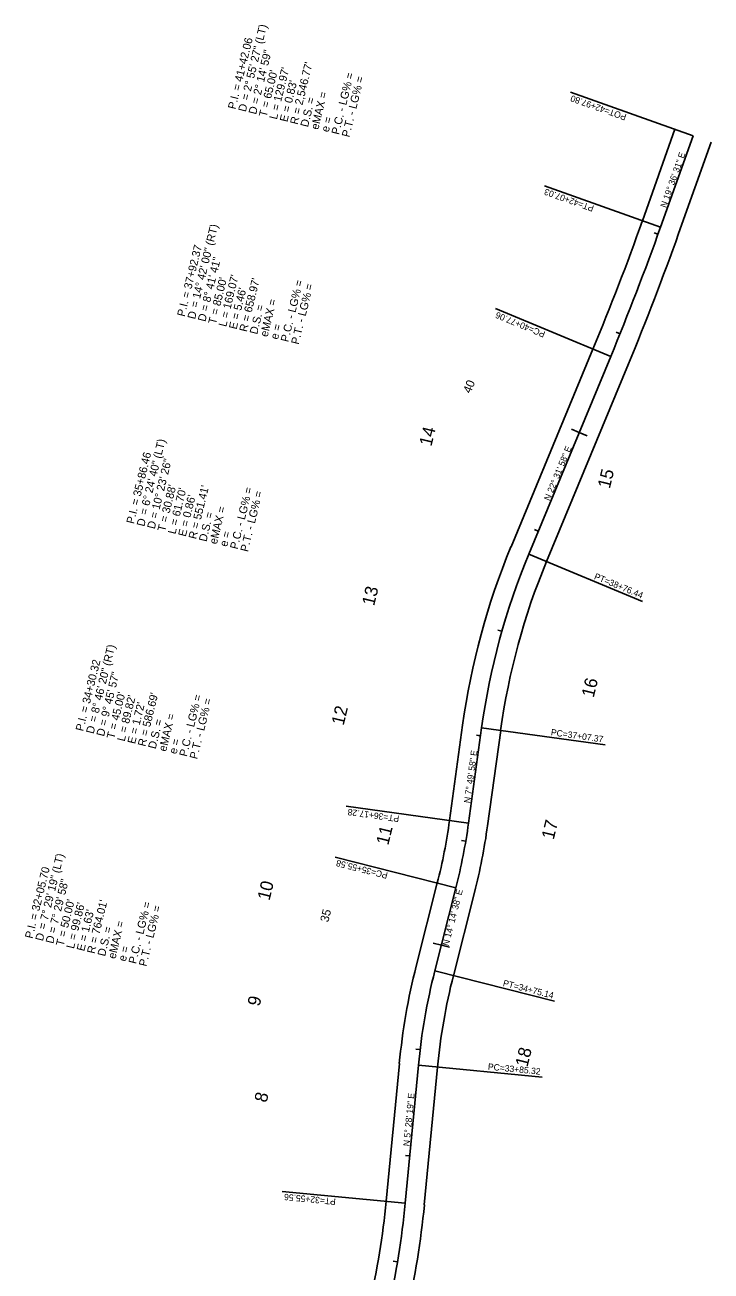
# Model space of a CAD drawing. Extents: x 1579440 to 1580937, y 1116374 to 1119566.
# Drawn here: x 1580144 to 1580787, y 1118399 to 1119566 of the extents above; entities that cross this region are included whole.
import ezdxf

# ---------------------------------------------------------------- set-up
doc = ezdxf.new("R2010")
doc.units = 0
for name, color, linetype in [('RD_HC_Cl', 7, 'Continuous'), ('RD_HC_Data', 7, 'Continuous'), ('RD_HC_Data_Tic', 7, 'Continuous'), ('RD_HC_TX_Sta50', 7, 'Continuous'), ('RD_PD_CstnLmt_TX', 7, 'Continuous'), ('RD_XS_Binder', 7, 'Continuous')]:
    doc.layers.add(name, color=color, linetype=linetype)

msp = doc.modelspace()

# ---------------------------------------------------------------- linework, layer by layer
at = {"layer": 'RD_HC_Cl'}
for p, q in [((1580739.9, 1119376.9), (1580770.4, 1119462.4)), ((1580739.9, 1119376.9), (1580770.4, 1119462.4)), ((1580616.3, 1119070.3), (1580693.2, 1119255.6)), ((1580616.3, 1119070.3), (1580693.2, 1119255.6)), ((1580559.9, 1118818.4), (1580572.1, 1118907.6)), ((1580559.9, 1118818.4), (1580572.1, 1118907.6)), ((1580528.3, 1118679.9), (1580548, 1118757.8)), ((1580528.3, 1118679.9), (1580548, 1118757.8)), ((1580500.5, 1118462.3), (1580512.9, 1118591.5)), ((1580500.5, 1118462.3), (1580512.9, 1118591.5))]:
    msp.add_line(p, q, dxfattribs=at)
for centre, radius, start, end in [((1578340.8, 1120231.6), 2546.8, 337.4673, 340.3913), ((1578340.8, 1120231.6), 2546.8, 337.4673, 340.3913), ((1581225, 1118817.8), 659, 157.4673, 172.1672), ((1581225, 1118817.8), 659, 157.4673, 172.1672), ((1580013.6, 1118893.5), 551.4, 345.756, 352.1672), ((1580013.6, 1118893.5), 551.4, 345.756, 352.1672), ((1581096.9, 1118535.5), 586.7, 165.756, 174.5281), ((1581096.9, 1118535.5), 586.7, 165.756, 174.5281), ((1579740, 1118535.1), 764, 347.0395, 354.5281), ((1579740, 1118535.1), 764, 347.0395, 354.5281)]:
    msp.add_arc(centre, radius, start, end, dxfattribs=at)
at = {"layer": 'RD_HC_Data'}
for p, q in [((1580770.4, 1119462.4), (1580655.4, 1119503.4)), ((1580739.9, 1119376.9), (1580631.1, 1119415.7)), ((1580693.2, 1119255.6), (1580585.2, 1119300.5)), ((1580616.3, 1119070.3), (1580723.1, 1119026)), ((1580572.1, 1118907.6), (1580688, 1118891.7)), ((1580559.9, 1118818.4), (1580445.2, 1118834.1)), ((1580548, 1118757.8), (1580434.9, 1118786.6)), ((1580528.3, 1118679.9), (1580640.4, 1118651.4)), ((1580512.9, 1118591.5), (1580628.9, 1118580.3)), ((1580500.5, 1118462.3), (1580385.1, 1118473.3))]:
    msp.add_line(p, q, dxfattribs=at)
at = {"layer": 'RD_HC_Data_Tic'}
for p, q in [((1580737.5, 1119370.3), (1580733.8, 1119371.6)), ((1580701.9, 1119276.9), (1580698.2, 1119278.4)), ((1580663.6, 1119184.5), (1580656.3, 1119187.5)), ((1580671, 1119181.4), (1580663.6, 1119184.5)), ((1580625.3, 1119092.1), (1580621.6, 1119093.6)), ((1580591.2, 1118998.2), (1580587.3, 1118999.3)), ((1580571.1, 1118900.3), (1580567.2, 1118900.9)), ((1580557.2, 1118801.3), (1580553.3, 1118802)), ((1580534.4, 1118704), (1580526.6, 1118705.9)), ((1580542.1, 1118702), (1580534.4, 1118704)), ((1580514.5, 1118606.1), (1580510.5, 1118606.5)), ((1580504.8, 1118506.5), (1580500.8, 1118506.9)), ((1580493.2, 1118407.2), (1580489.3, 1118407.9))]:
    msp.add_line(p, q, dxfattribs=at)
at = {"layer": 'RD_XS_Binder'}
for p, q in [((1580722.9, 1119382.9), (1580753.4, 1119468.5)), ((1580756.8, 1119370.9), (1580787.3, 1119456.4)), ((1580599.7, 1119077.2), (1580676.5, 1119262.5)), ((1580632.9, 1119063.4), (1580709.8, 1119248.7)), ((1580542, 1118820.8), (1580554.3, 1118910.1)), ((1580577.7, 1118815.9), (1580590, 1118905.2)), ((1580510.8, 1118684.3), (1580530.6, 1118762.3)), ((1580545.7, 1118675.4), (1580565.5, 1118753.4)), ((1580482.6, 1118464), (1580495, 1118593.2)), ((1580518.4, 1118460.6), (1580530.8, 1118589.7))]:
    msp.add_line(p, q, dxfattribs=at)
for centre, radius, start, end in [((1578340.8, 1120231.6), 2528.8, 337.4673, 340.3913), ((1578340.8, 1120231.6), 2564.8, 337.4673, 340.3913), ((1581225, 1118817.8), 677, 157.4673, 172.1672), ((1581225, 1118817.8), 641, 157.4673, 172.1672), ((1580013.6, 1118893.5), 533.4, 345.756, 352.1672), ((1580013.6, 1118893.5), 569.4, 345.756, 352.1672), ((1581096.9, 1118535.5), 604.7, 165.756, 174.5281), ((1581096.9, 1118535.5), 568.7, 165.756, 174.5281), ((1579740, 1118535.1), 746, 347.0395, 354.5281), ((1579740, 1118535.1), 782, 347.0395, 354.5281)]:
    msp.add_arc(centre, radius, start, end, dxfattribs=at)

# ---------------------------------------------------------------- texts
at = {"layer": 'RD_HC_Data'}
for s, height, rotation, p in [('    = 2%%d 55\' 27" (LT)', 7.5, 76.2368, (1580351, 1119484.4)), ('P.I. = 41+42.06', 7.5, 76.2368, (1580341.3, 1119486.8)), ('D = 2%%d 14\' 59"', 7.5, 76.2368, (1580360.7, 1119482)), ("R = 2,546.77'", 7.5, 76.2368, (1580399.6, 1119472.5)), ("T = 65.00'", 7.5, 76.2368, (1580370.4, 1119479.6)), ("L = 129.97'", 7.5, 76.2368, (1580380.1, 1119477.3)), ('P.C. - LG% = ', 7.5, 76.2368, (1580438.4, 1119463)), ('P.T. - LG% = ', 7.5, 76.2368, (1580448.1, 1119460.6)), ("E = 0.83'", 7.5, 76.2368, (1580389.9, 1119474.9)), ('D.S. = ', 7.5, 76.2368, (1580409.3, 1119470.1)), ('eMAX = ', 7.5, 76.2368, (1580419, 1119467.7)), ('POT=42+97.80', 6, 160.3913, (1580708.5, 1119482.3)), ('D', 7.5, 76.2368, (1580351, 1119484.4)), ('e = ', 7.5, 76.2368, (1580428.7, 1119465.4)), ('N 19%%d 36\' 31" E', 6, 70.3913, (1580745.1, 1119394.5)), ('PT=42+07.03', 6, 160.3913, (1580678, 1119396.8)), ('    = 14%%d 42\' 00" (RT)', 7.5, 76.2368, (1580303.4, 1119290.1)), ('P.I. = 37+92.37', 7.5, 76.2368, (1580293.7, 1119292.5)), ('D = 8%%d 41\' 41"', 7.5, 76.2368, (1580313.1, 1119287.8)), ("T = 85.00'", 7.5, 76.2368, (1580322.9, 1119285.4)), ("L = 169.07'", 7.5, 76.2368, (1580332.6, 1119283)), ("E = 5.46'", 7.5, 76.2368, (1580342.3, 1119280.6)), ("R = 658.97'", 7.5, 76.2368, (1580352, 1119278.2)), ('P.C. - LG% = ', 7.5, 76.2368, (1580390.8, 1119268.7)), ('P.T. - LG% = ', 7.5, 76.2368, (1580400.6, 1119266.4)), ('eMAX = ', 7.5, 76.2368, (1580371.4, 1119273.5)), ('D', 7.5, 76.2368, (1580303.4, 1119290.1)), ('D.S. = ', 7.5, 76.2368, (1580361.7, 1119275.9)), ('PC=40+77.06', 6, 157.4673, (1580632.4, 1119278.7)), ('e = ', 7.5, 76.2368, (1580381.1, 1119271.1)), ('    = 6%%d 24\' 40" (LT)', 7.5, 76.2368, (1580255.8, 1119095.9)), ('N 22%%d 31\' 58" E', 6, 67.4673, (1580635.9, 1119119.9)), ('P.I. = 35+86.46', 7.5, 76.2368, (1580246.1, 1119098.3)), ('D = 10%%d 23\' 26"', 7.5, 76.2368, (1580265.6, 1119093.5)), ("T = 30.88'", 7.5, 76.2368, (1580275.3, 1119091.1)), ("L = 61.70'", 7.5, 76.2368, (1580285, 1119088.7)), ("R = 551.41'", 7.5, 76.2368, (1580304.4, 1119084)), ('P.C. - LG% = ', 7.5, 76.2368, (1580343.3, 1119074.5)), ("E = 0.86'", 7.5, 76.2368, (1580294.7, 1119086.4)), ('P.T. - LG% = ', 7.5, 76.2368, (1580353, 1119072.1)), ('D.S. = ', 7.5, 76.2368, (1580314.1, 1119081.6)), ('eMAX = ', 7.5, 76.2368, (1580323.8, 1119079.2)), ('D', 7.5, 76.2368, (1580255.8, 1119095.9)), ('e = ', 7.5, 76.2368, (1580333.5, 1119076.9)), ('PT=38+76.44', 6, 337.4673, (1580677.1, 1119047.3)), ('    = 8%%d 46\' 20" (RT)', 7.5, 76.2368, (1580208.3, 1118901.6)), ('P.I. = 34+30.32', 7.5, 76.2368, (1580198.5, 1118904)), ('D = 9%%d 45\' 57"', 7.5, 76.2368, (1580218, 1118899.2)), ("T = 45.00'", 7.5, 76.2368, (1580227.7, 1118896.9)), ("L = 89.82'", 7.5, 76.2368, (1580237.4, 1118894.5)), ("R = 586.69'", 7.5, 76.2368, (1580256.8, 1118889.7)), ('P.C. - LG% = ', 7.5, 76.2368, (1580295.7, 1118880.2)), ('P.T. - LG% = ', 7.5, 76.2368, (1580305.4, 1118877.8)), ("E = 1.72'", 7.5, 76.2368, (1580247.1, 1118892.1)), ('D', 7.5, 76.2368, (1580208.3, 1118901.6)), ('D.S. = ', 7.5, 76.2368, (1580266.5, 1118887.4)), ('eMAX = ', 7.5, 76.2368, (1580276.3, 1118885)), ('PC=37+07.37', 6, 352.1672, (1580636.8, 1118900.7)), ('e = ', 7.5, 76.2368, (1580286, 1118882.6)), ('N 7%%d 49\' 58" E', 6, 82.1672, (1580561.4, 1118836.8)), ('PT=36+17.28', 6, 172.1672, (1580495.2, 1118825.2)), ('    = 7%%d 29\' 19" (LT)', 7.5, 76.2368, (1580160.7, 1118707.4)), ('PC=35+55.58', 6, 165.756, (1580484.6, 1118771.9)), ('P.I. = 32+05.70', 7.5, 76.2368, (1580151, 1118709.7)), ('D = 7%%d 29\' 58"', 7.5, 76.2368, (1580170.4, 1118705)), ("T = 50.00'", 7.5, 76.2368, (1580180.1, 1118702.6)), ("R = 764.01'", 7.5, 76.2368, (1580209.2, 1118695.5)), ('N 14%%d 14\' 38" E', 6, 75.756, (1580541.2, 1118702.8)), ("L = 99.86'", 7.5, 76.2368, (1580189.8, 1118700.2)), ("E = 1.63'", 7.5, 76.2368, (1580199.5, 1118697.9)), ('P.C. - LG% = ', 7.5, 76.2368, (1580248.1, 1118686)), ('P.T. - LG% = ', 7.5, 76.2368, (1580257.8, 1118683.6)), ('eMAX = ', 7.5, 76.2368, (1580228.7, 1118690.7)), ('D', 7.5, 76.2368, (1580160.7, 1118707.4)), ('D.S. = ', 7.5, 76.2368, (1580219, 1118693.1)), ('e = ', 7.5, 76.2368, (1580238.4, 1118688.3)), ('PT=34+75.14', 6, 345.756, (1580591.7, 1118665.8)), ('PC=33+85.32', 6, 354.5281, (1580577.8, 1118587.3)), ('N 5%%d 28\' 19" E', 6, 84.5281, (1580504.5, 1118515.4)), ('PT=32+55.56', 6, 174.5281, (1580435.6, 1118466.5))]:
    msp.add_text(s, height=height, rotation=rotation, dxfattribs=at).set_placement(p)
at = {"layer": 'RD_HC_TX_Sta50'}
for s, rotation, p in [('40', 67.4673, (1580561.7, 1119220.5)), ('35', 75.756, (1580428.3, 1118725))]:
    msp.add_text(s, height=8, rotation=rotation, dxfattribs=at).set_placement(p)
at = {"layer": 'RD_PD_CstnLmt_TX'}
for s, p in [('14', (1580525, 1119170.8)), ('15', (1580692.3, 1119131.2)), ('13', (1580471.3, 1119021.3)), ('16', (1580677.2, 1118935.4)), ('12', (1580442.7, 1118909.3)), ('17', (1580639.7, 1118802.3)), ('11', (1580484.6, 1118797.1)), ('10', (1580373.2, 1118745.2)), ('9', (1580363.9, 1118646.1)), ('18', (1580615.1, 1118589.2)), ('8', (1580370.4, 1118555.9))]:
    msp.add_text(s, height=12, rotation=76.2368, dxfattribs=at).set_placement(p)

doc.saveas('drawing.dxf')
